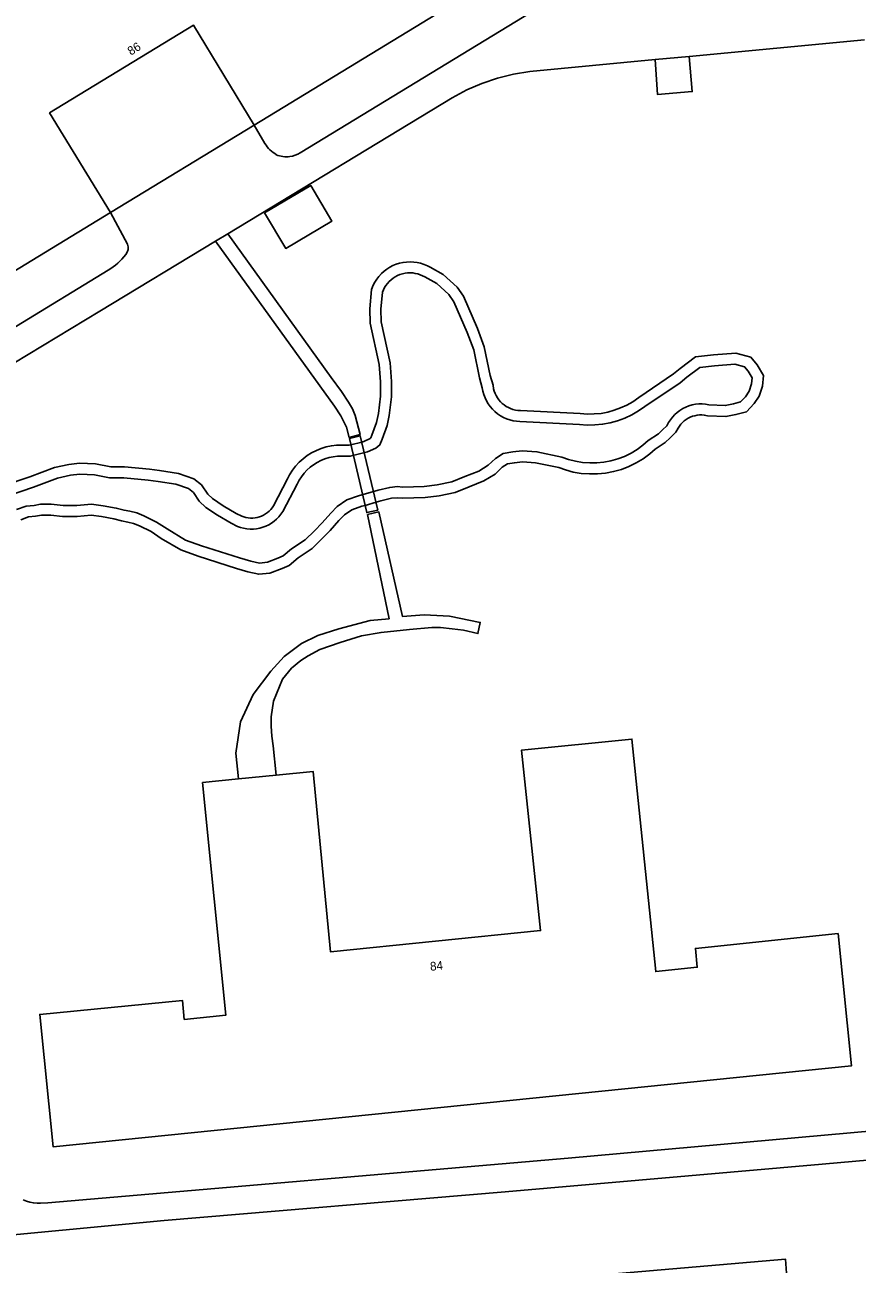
# Model space of a CAD drawing. Extents: x 158132 to 159658, y 385257 to 387209.
# Drawn here: x 158463 to 158558.9, y 386585.2 to 386727.8 of the extents above; entities that cross this region are included whole.
import ezdxf

# ---------------------------------------------------------------- set-up
doc = ezdxf.new("R2010")
doc.units = 0
for name, color, linetype in [('IMGEO_Dek', 7, 'Continuous'), ('IMGEO_Groenvoorziening', 7, 'Continuous'), ('IMGEO_Meer_plas_ven_vijver', 7, 'Continuous'), ('IMGEO_Pand', 7, 'Continuous'), ('IMGEO_Pand_nummerreeks', 7, 'Continuous'), ('IMGEO_Rijbaan_lokaal_gesloten', 7, 'Continuous'), ('IMGEO_Voetpad_gesloten', 7, 'Continuous'), ('IMGEO_Voetpad_onverhard', 7, 'Continuous')]:
    doc.layers.add(name, color=color, linetype=linetype)

msp = doc.modelspace()

# ---------------------------------------------------------------- linework, layer by layer
at = {"layer": 'IMGEO_Dek'}
msp.add_lwpolyline([(158503.68, 386671.97), (158501.64, 386680.52), (158500.39, 386680.22), (158502.4, 386671.7)], close=True, dxfattribs=at)
at = {"layer": 'IMGEO_Groenvoorziening'}
for points in [[(158539.53, 386724.21), (158539.87, 386720.16), (158535.87, 386719.82), (158535.59, 386723.84)], [(158460.55, 386674.78), (158463.61, 386675.83), (158466.43, 386676.88), (158468.1, 386677.25), (158469.31, 386677.39), (158471.18, 386677.3), (158472.92, 386676.98), (158474.5, 386676.95), (158477.38, 386676.69), (158478.55, 386676.53), (158480.72, 386676.19), (158482.49, 386675.58), (158483.38, 386674.89), (158484.08, 386673.83), (158484.65, 386673.3), (158485.88, 386672.48), (158487.37, 386671.6), (158488.02, 386671.28), (158488.24, 386671.2), (158488.49, 386671.13), (158488.75, 386671.08), (158489.01, 386671.06), (158489.27, 386671.07), (158489.53, 386671.09), (158489.79, 386671.14), (158490.04, 386671.21), (158490.28, 386671.3), (158490.52, 386671.41), (158490.74, 386671.54), (158490.96, 386671.7), (158491.15, 386671.87), (158491.34, 386672.05), (158491.5, 386672.26), (158491.64, 386672.46), (158493.25, 386675.57), (158493.51, 386676.06), (158493.83, 386676.57), (158494.2, 386677.04), (158494.61, 386677.49), (158495.06, 386677.89), (158495.54, 386678.26), (158496.05, 386678.58), (158496.59, 386678.85), (158497.15, 386679.08), (158497.73, 386679.25), (158498.32, 386679.38), (158498.92, 386679.45), (158499.49, 386679.47), (158500.35, 386679.46), (158500.55, 386679.51), (158501.81, 386679.82), (158502.04, 386679.87), (158502.77, 386680.22), (158502.86, 386680.29), (158502.99, 386680.59), (158503.51, 386682.06), (158503.73, 386683.1), (158503.97, 386685.1), (158503.98, 386686.73), (158503.84, 386688.75), (158502.78, 386693.51), (158502.74, 386695.15), (158502.95, 386697.36), (158503.15, 386697.86), (158503.34, 386698.23), (158503.56, 386698.57), (158503.8, 386698.89), (158504.08, 386699.2), (158504.38, 386699.47), (158504.71, 386699.72), (158505.05, 386699.94), (158505.41, 386700.13), (158505.79, 386700.29), (158506.18, 386700.41), (158506.58, 386700.49), (158506.98, 386700.54), (158507.39, 386700.56), (158507.8, 386700.54), (158508.21, 386700.48), (158508.6, 386700.39), (158508.99, 386700.27), (158509.37, 386700.1), (158509.69, 386699.93), (158511.19, 386699.11), (158512.82, 386697.65), (158513.55, 386696.59), (158515.15, 386692.88), (158515.93, 386690.79), (158516.61, 386687.49), (158516.93, 386686.35), (158517, 386685.96), (158517.08, 386685.68), (158517.18, 386685.41), (158517.3, 386685.16), (158517.44, 386684.91), (158517.61, 386684.68), (158517.79, 386684.46), (158517.99, 386684.27), (158518.21, 386684.09), (158518.45, 386683.92), (158518.7, 386683.79), (158518.96, 386683.67), (158519.22, 386683.57), (158519.5, 386683.5), (158519.78, 386683.46), (158520.1, 386683.43), (158526.95, 386683.11), (158527.81, 386683.04), (158528.59, 386683.05), (158529.37, 386683.12), (158530.14, 386683.26), (158530.89, 386683.47), (158531.62, 386683.74), (158532.33, 386684.07), (158533.01, 386684.46), (158533.7, 386684.95), (158537.71, 386687.67), (158538.47, 386688.27), (158540.26, 386689.63), (158542.31, 386689.84), (158544.88, 386690.06), (158546.61, 386689.58), (158547.36, 386688.72), (158548.07, 386687.48), (158547.95, 386686.26), (158547.56, 386685.11), (158547, 386684.24), (158546.1, 386683.29), (158544.9, 386682.98), (158543.75, 386682.74), (158541.64, 386682.85), (158541.24, 386682.92), (158540.97, 386682.94), (158540.69, 386682.93), (158540.42, 386682.91), (158540.15, 386682.85), (158539.89, 386682.78), (158539.64, 386682.68), (158539.39, 386682.55), (158539.16, 386682.41), (158538.94, 386682.25), (158538.74, 386682.06), (158538.55, 386681.86), (158538.39, 386681.65), (158538.24, 386681.41), (158537.99, 386680.94), (158537.33, 386680.29), (158536.75, 386679.78), (158535.59, 386678.98), (158534.98, 386678.45), (158534.23, 386677.9), (158533.42, 386677.41), (158532.58, 386677), (158531.71, 386676.67), (158530.81, 386676.41), (158529.89, 386676.24), (158528.95, 386676.15), (158528.02, 386676.14), (158527.08, 386676.21), (158526.16, 386676.36), (158525.26, 386676.6), (158524.51, 386676.87), (158521.81, 386677.44), (158520.32, 386677.54), (158519.4, 386677.44), (158518.58, 386677.3), (158518, 386676.93), (158517.16, 386676.13), (158515.89, 386675.34), (158514.17, 386674.66), (158512.56, 386674.02), (158510.72, 386673.63), (158509.11, 386673.42), (158507.8, 386673.4), (158506.47, 386673.35), (158505.94, 386673.41), (158505.26, 386673.34), (158504.01, 386673.05), (158503.46, 386672.89), (158502.21, 386672.53), (158501.84, 386672.42), (158500.66, 386672), (158499.82, 386671.44), (158499.18, 386670.77), (158498.2, 386669.65), (158497.27, 386668.7), (158496.11, 386667.56), (158494.5, 386666.49), (158493.45, 386665.61), (158492.64, 386665.26), (158491.25, 386664.72), (158489.95, 386664.59), (158488.72, 386664.88), (158487.39, 386665.27), (158482.97, 386666.66), (158480.97, 386667.39), (158478.73, 386668.73), (158477.57, 386669.51), (158476.22, 386670.17), (158475.54, 386670.43), (158474.87, 386670.6), (158474.17, 386670.73), (158473.27, 386670.98), (158471.85, 386671.24), (158470.68, 386671.38), (158469.05, 386671.23), (158467.38, 386671.26), (158466.02, 386671.38), (158464.93, 386671.38), (158464.25, 386671.27), (158463.46, 386671.2), (158462.57, 386670.88)], [(158382.28, 386617.86), (158383.41, 386617.14), (158384.42, 386616.07), (158386.16, 386613.65), (158387.09, 386611.03), (158391.36, 386572.1), (158550.62, 386585.75), (158550.77, 386583.59)]]:
    msp.add_lwpolyline(points, dxfattribs=at)
at = {"layer": 'IMGEO_Meer_plas_ven_vijver'}
for points in [[(158464.04, 386674.63), (158466.79, 386675.66), (158468.3, 386676), (158469.35, 386676.11), (158471.03, 386676.04), (158472.79, 386675.71), (158474.43, 386675.68), (158477.24, 386675.43), (158478.37, 386675.28), (158480.42, 386674.95), (158481.88, 386674.45), (158482.44, 386674.02), (158483.11, 386673.01), (158483.86, 386672.3), (158485.2, 386671.4), (158486.77, 386670.48), (158487.51, 386670.11), (158487.86, 386669.98), (158488.22, 386669.89), (158488.59, 386669.82), (158488.96, 386669.79), (158489.34, 386669.8), (158489.71, 386669.83), (158490.07, 386669.9), (158490.43, 386670), (158490.78, 386670.13), (158491.12, 386670.29), (158491.44, 386670.48), (158491.74, 386670.7), (158492.02, 386670.94), (158492.29, 386671.21), (158492.52, 386671.5), (158492.73, 386671.81), (158494.37, 386674.98), (158494.6, 386675.42), (158494.87, 386675.83), (158495.17, 386676.22), (158495.51, 386676.58), (158495.87, 386676.91), (158496.26, 386677.21), (158496.68, 386677.47), (158497.12, 386677.7), (158497.57, 386677.88), (158498.05, 386678.02), (158498.53, 386678.13), (158499.02, 386678.18), (158499.51, 386678.2), (158500.49, 386678.19), (158502.47, 386678.67), (158503.43, 386679.12), (158503.9, 386679.48), (158504.18, 386680.13), (158504.73, 386681.72), (158504.99, 386682.89), (158505.24, 386685.02), (158505.25, 386686.77), (158505.1, 386688.93), (158504.05, 386693.66), (158504.01, 386695.11), (158504.2, 386697.06), (158504.31, 386697.33), (158504.45, 386697.6), (158504.6, 386697.85), (158504.78, 386698.08), (158504.98, 386698.3), (158505.2, 386698.5), (158505.43, 386698.68), (158505.68, 386698.84), (158505.95, 386698.98), (158506.22, 386699.09), (158506.51, 386699.18), (158506.8, 386699.24), (158507.09, 386699.28), (158507.39, 386699.29), (158507.68, 386699.28), (158507.98, 386699.23), (158508.26, 386699.17), (158508.55, 386699.08), (158508.82, 386698.96), (158509.08, 386698.82), (158510.45, 386698.06), (158511.86, 386696.81), (158512.43, 386695.97), (158513.97, 386692.41), (158514.71, 386690.44), (158515.38, 386687.2), (158515.69, 386686.06), (158515.76, 386685.67), (158515.87, 386685.29), (158516.01, 386684.92), (158516.18, 386684.56), (158516.38, 386684.22), (158516.61, 386683.9), (158516.86, 386683.6), (158517.14, 386683.32), (158517.45, 386683.07), (158517.78, 386682.85), (158518.12, 386682.65), (158518.48, 386682.49), (158518.86, 386682.36), (158519.24, 386682.26), (158519.63, 386682.2), (158520.02, 386682.17), (158526.87, 386681.84), (158527.76, 386681.77), (158528.65, 386681.78), (158529.54, 386681.86), (158530.42, 386682.02), (158531.28, 386682.26), (158532.11, 386682.57), (158532.92, 386682.94), (158533.69, 386683.39), (158534.42, 386683.91), (158538.46, 386686.65), (158539.25, 386687.27), (158540.74, 386688.41), (158542.43, 386688.57), (158544.76, 386688.78), (158545.9, 386688.46), (158546.31, 386687.98), (158546.76, 386687.2), (158546.7, 386686.52), (158546.41, 386685.66), (158545.99, 386685.03), (158545.43, 386684.43), (158544.61, 386684.22), (158543.66, 386684.02), (158541.78, 386684.11), (158541.39, 386684.18), (158541.01, 386684.21), (158540.62, 386684.2), (158540.23, 386684.16), (158539.85, 386684.09), (158539.48, 386683.98), (158539.12, 386683.84), (158538.77, 386683.66), (158538.44, 386683.46), (158538.13, 386683.23), (158537.85, 386682.97), (158537.58, 386682.68), (158537.35, 386682.38), (158537.14, 386682.05), (158536.96, 386681.7), (158536.46, 386681.22), (158535.97, 386680.78), (158534.81, 386679.98), (158534.19, 386679.44), (158533.52, 386678.95), (158532.82, 386678.53), (158532.08, 386678.17), (158531.31, 386677.88), (158530.51, 386677.65), (158529.7, 386677.5), (158528.88, 386677.41), (158528.06, 386677.41), (158527.24, 386677.47), (158526.43, 386677.61), (158525.63, 386677.81), (158524.85, 386678.09), (158521.99, 386678.7), (158520.3, 386678.82), (158519.22, 386678.7), (158518.11, 386678.51), (158517.21, 386677.94), (158516.38, 386677.14), (158515.31, 386676.48), (158513.7, 386675.85), (158512.19, 386675.24), (158510.5, 386674.89), (158509.02, 386674.68), (158507.78, 386674.67), (158506.51, 386674.63), (158505.93, 386674.68), (158505.05, 386674.59), (158503.69, 386674.28), (158501.45, 386673.63), (158500.09, 386673.15), (158498.99, 386672.41), (158498.25, 386671.63), (158497.27, 386670.52), (158496.37, 386669.6), (158495.3, 386668.55), (158493.74, 386667.51), (158492.77, 386666.7), (158492.16, 386666.43), (158490.95, 386665.97), (158490.04, 386665.88), (158489.05, 386666.11), (158487.76, 386666.48), (158483.38, 386667.86), (158481.52, 386668.54), (158479.41, 386669.81), (158478.2, 386670.61), (158476.73, 386671.33), (158475.93, 386671.65), (158475.13, 386671.84), (158474.45, 386671.96), (158473.56, 386672.22), (158472.04, 386672.49), (158470.7, 386672.65), (158469, 386672.5), (158467.45, 386672.52), (158466.07, 386672.65), (158464.83, 386672.65), (158464.1, 386672.53), (158463.18, 386672.45), (158462.07, 386672.05)], [(158460.98, 386673.58), (158464.04, 386674.63)]]:
    msp.add_lwpolyline(points, dxfattribs=at)
at = {"layer": 'IMGEO_Pand'}
for points in [[(158489.45, 386716.31), (158539.03, 386746.51), (158523.53, 386771.96), (158404.59, 386699.52), (158420.09, 386674.06), (158472.88, 386706.22)], [(158489.45, 386716.31), (158482.45, 386727.79), (158465.88, 386717.7), (158472.88, 386706.22)], [(158490.63, 386706.21), (158493.06, 386702.1), (158498.36, 386705.23), (158495.94, 386709.34), (158490.63, 386706.21)], [(158491.95, 386641.48), (158496.21, 386641.91), (158498.22, 386621.13), (158522.4, 386623.58), (158520.2, 386644.34), (158532.92, 386645.63), (158535.67, 386618.86), (158540.45, 386619.35), (158540.23, 386621.53), (158556.65, 386623.24), (158558.2, 386608.01), (158466.28, 386598.7), (158464.74, 386613.93), (158481.17, 386615.54), (158481.39, 386613.36), (158486.17, 386613.85), (158483.5, 386640.62), (158487.61, 386641.04)], [(158487.61, 386641.04), (158491.95, 386641.48)]]:
    msp.add_lwpolyline(points, dxfattribs=at)
at = {"layer": 'IMGEO_Rijbaan_lokaal_gesloten'}
for points in [[(158549.96, 386782.63), (158547.63, 386781.44), (158552.84, 386765.8), (158554.79, 386760.51), (158555.58, 386757.51), (158555.7, 386756.79), (158555.91, 386753.62), (158555.83, 386753.42), (158554.92, 386751.92), (158554.53, 386751.14), (158553.73, 386750.16), (158552.38, 386748.51), (158551.24, 386747.5), (158549.85, 386746.68), (158494.74, 386713.11)], [(158559.68, 386726.12), (158539.53, 386724.21)], [(158535.59, 386723.84), (158539.53, 386724.21)], [(158535.59, 386723.84), (158521.17, 386722.48), (158519.29, 386722.17), (158517.45, 386721.71), (158515.65, 386721.1), (158513.91, 386720.34), (158512.24, 386719.43), (158486.39, 386703.78)], [(158489.45, 386716.31), (158472.88, 386706.22)], [(158490.66, 386714.18), (158489.45, 386716.31)], [(158472.88, 386706.22), (158474.85, 386702.59)], [(158484.98, 386702.93), (158471.68, 386694.88), (158450.16, 386681.91)], [(158484.98, 386702.93), (158486.39, 386703.78)], [(158472.62, 386699.61), (158462.05, 386693.17), (158441.23, 386680.73), (158440.62, 386680.34), (158440.04, 386679.91), (158439.49, 386679.42), (158438.99, 386678.9), (158438.54, 386678.33), (158438.13, 386677.73), (158437.77, 386677.1), (158437.47, 386676.44), (158437.22, 386675.76), (158436.94, 386674.64), (158436.23, 386671.33), (158435.83, 386667.97), (158435.76, 386664.58), (158438.72, 386631.16), (158440.23, 386615.48)], [(158462.83, 386592.58), (158463.22, 386592.43), (158463.62, 386592.32), (158464.02, 386592.24), (158464.43, 386592.2), (158464.85, 386592.2), (158465.67, 386592.24), (158525.58, 386597.37), (158602.14, 386604.25)], [(158455.62, 386587.98), (158479.06, 386590.22), (158518.31, 386593.52), (158554.82, 386596.68), (158594.96, 386600.25)]]:
    msp.add_lwpolyline(points, dxfattribs=at)
for centre, radius, start, end in [((158494.12, 386716.4), 4.11, 212.7322, 238.7559), ((158493.2, 386715.9), 3.25, 247.9932, 275.9736), ((158493.09, 386715.76), 3.12, 278.313, 301.9062), ((158469.25, 386705.46), 6.75, 299.9611, 323.0843), ((158473.74, 386702.18), 1.19, 319.7139, 20.2757)]:
    msp.add_arc(centre, radius, start, end, dxfattribs=at)
at = {"layer": 'IMGEO_Voetpad_gesloten'}
msp.add_lwpolyline([(158503.68, 386671.97), (158501.64, 386680.52), (158500.39, 386680.22), (158502.4, 386671.7), (158503.68, 386671.97)], dxfattribs=at)
at = {"layer": 'IMGEO_Voetpad_onverhard'}
for points in [[(158486.39, 386703.78), (158498.3, 386687.23), (158499.47, 386685.62), (158500.31, 386684.39), (158500.75, 386683.65), (158501.06, 386682.86), (158501.64, 386680.67), (158500.36, 386680.35), (158500.07, 386681.51), (158499.78, 386682.08), (158499.4, 386682.84), (158498.67, 386683.95), (158484.98, 386702.93)], [(158487.61, 386641.04), (158487.31, 386644.01), (158487.86, 386647.61), (158489.3, 386650.75), (158491.35, 386653.46), (158492.88, 386655.12), (158494.89, 386656.64), (158496.75, 386657.55), (158499.16, 386658.31), (158502.77, 386659.26), (158504.97, 386659.48), (158502.48, 386671.46), (158503.79, 386671.77), (158506.5, 386659.74), (158508.99, 386659.94), (158511.91, 386659.79), (158515.46, 386659.06), (158515.19, 386657.76), (158513.52, 386658.18), (158512.21, 386658.32), (158510.88, 386658.47), (158509.87, 386658.47), (158507.33, 386658.25), (158504.04, 386657.9), (158501.8, 386657.52), (158499.35, 386656.75), (158497, 386655.93), (158495.64, 386655.22), (158494.8, 386654.68), (158493.72, 386653.77), (158492.7, 386652.53), (158491.64, 386649.99), (158491.39, 386648.17), (158491.39, 386647.12), (158491.46, 386645.94), (158491.61, 386644.85), (158491.95, 386641.48)]]:
    msp.add_lwpolyline(points, dxfattribs=at)

# ---------------------------------------------------------------- texts
at = {"layer": 'IMGEO_Pand_nummerreeks'}
for s, rotation, p in [('86', 31.9997, (158475.24, 386724.28)), ('84', 5.5176, (158509.73, 386618.95))]:
    msp.add_text(s, height=1, rotation=rotation, dxfattribs=at).set_placement(p)

doc.saveas('drawing.dxf')
